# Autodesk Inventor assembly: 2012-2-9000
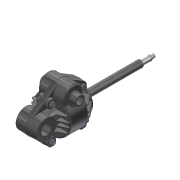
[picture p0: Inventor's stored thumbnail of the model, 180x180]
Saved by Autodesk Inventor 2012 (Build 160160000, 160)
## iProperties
Created: 2011-12
Part Number: 2012-2-9000
Document SubType Name: Assembly
Designer: dmm70056
Author: dmm70056
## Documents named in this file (8)
- K:\Autodesk CMU Course\Week 6 - Inventor Drawings\Problem Set Assignment\Files\2012-2-9000.iam
- K:\Autodesk CMU Course\Week 6 - Inventor Drawings\Problem Set Assignment\Files\2012-2-9003.ipt
- K:\Autodesk CMU Course\Week 6 - Inventor Drawings\Problem Set Assignment\Files\2012-2-9004.ipt
- K:\Autodesk CMU Course\Week 6 - Inventor Drawings\Problem Set Assignment\Files\2012-2-9007.iam
- K:\Autodesk CMU Course\Week 6 - Inventor Drawings\Problem Set Assignment\Files\2012-2-9001.ipt
- K:\Autodesk CMU Course\Week 6 - Inventor Drawings\Problem Set Assignment\Files\2012-2-9006.ipt
- K:\Autodesk CMU Course\Week 6 - Inventor Drawings\Problem Set Assignment\Files\2012-2-9005.ipt
- K:\Autodesk CMU Course\Week 6 - Inventor Drawings\Problem Set Assignment\Files\2012-2-9002.ipt
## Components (10 placed, 7 different names)
1. 2012-2-9003:1 — Insert:1, Mate:1, Insert:2, Insert:3, Insert:4, Insert:5, Mate:2, Mate:3
2. 2012-2-9002:1 — Insert:1, Mate:1
3. AS 1427 - Metric M3 x 12:1 — Insert:2
4. AS 1427 - Metric M3 x 12:2 — Insert:5
5. AS 1427 - Metric M3 x 12:3 — Insert:4
6. AS 1427 - Metric M3 x 12:4 — Insert:3
7. Worm Gears:1 [sub-assembly] — Mate:2, Mate:3, Mate:4, Insert:6, Mate:5, Flush:1
8. Shaft:1 — Mate:4, Mate:5, Flush:1, Mate:6, Tangent:1
9. 2012-2-9006:1 — Insert:6
10. 2012-2-9005:1 — Mate:6, Tangent:1
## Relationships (14: Insert 6, Mate 6, Flush 1, Tangent 1)
- Insert:1: 2012-2-9003:1 ↔ 2012-2-9002:1
- Mate:1: 2012-2-9003:1 ↔ 2012-2-9002:1
- Insert:2: 2012-2-9003:1 ↔ AS 1427 - Metric M3 x 12:1
- Insert:3: 2012-2-9003:1 ↔ AS 1427 - Metric M3 x 12:4
- Insert:4: 2012-2-9003:1 ↔ AS 1427 - Metric M3 x 12:3
- Insert:5: 2012-2-9003:1 ↔ AS 1427 - Metric M3 x 12:2
- Mate:2: 2012-2-9003:1 ↔ Worm Gears:1
- Mate:3: 2012-2-9003:1 ↔ Worm Gears:1
- Mate:4: Worm Gears:1 ↔ Shaft:1
- Insert:6: Worm Gears:1 ↔ 2012-2-9006:1
- Mate:5: Worm Gears:1 ↔ Shaft:1
- Flush:1: Worm Gears:1 ↔ Shaft:1
- Mate:6: Shaft:1 ↔ 2012-2-9005:1
- Tangent:1: Shaft:1 ↔ 2012-2-9005:1
